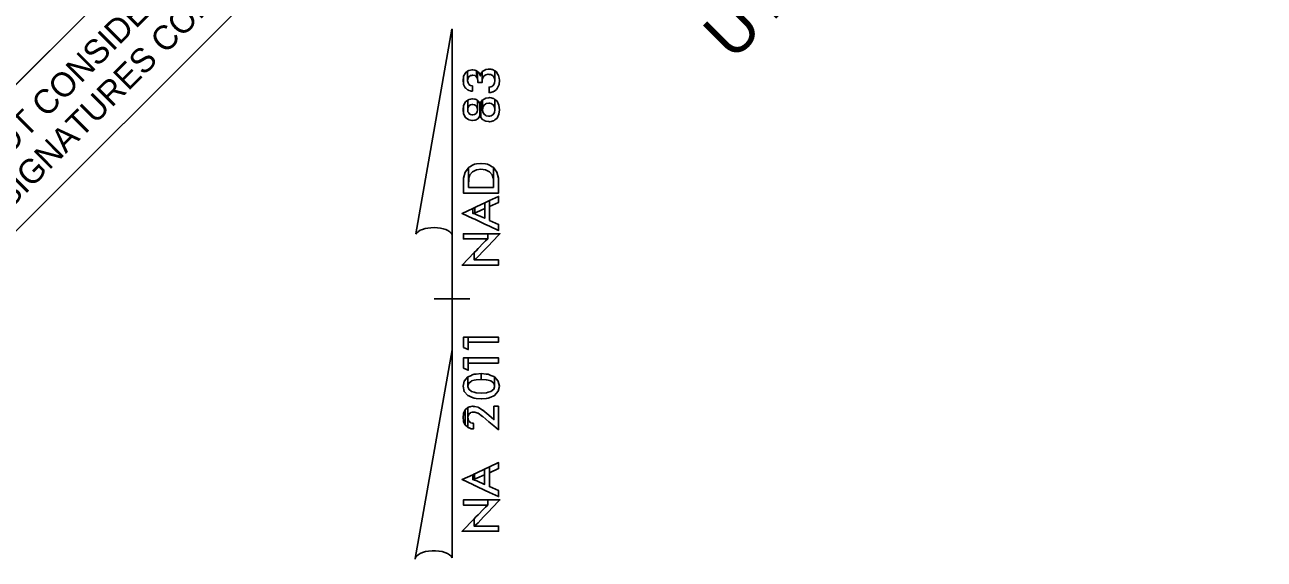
# Model space of a CAD drawing. Extents: x 1439200 to 1641361, y 392889 to 606444.
# Drawn here: x 1640975.9 to 1641088.2, y 393519.9 to 393568.3 of the extents above; entities that cross this region are included whole.
import ezdxf

# ---------------------------------------------------------------- set-up
doc = ezdxf.new("R2010")
doc.units = 0
for name, color, linetype in [('North Arrow NAD83 CELL', 7, 'Continuous'), ('Old_Level_60', 7, 'Continuous'), ('Sheet Sticker Exception Certification CELL', 7, 'Continuous'), ('UC Plan Sheet 34 CELL', 7, 'Continuous')]:
    doc.layers.add(name, color=color, linetype=linetype)

msp = doc.modelspace()

# ---------------------------------------------------------------- linework, layer by layer
at = {"layer": 'North Arrow NAD83 CELL'}
for p, q in [((1641011.28, 393549.32), (1641014.57, 393567.86)), ((1641014.59, 393567.86), (1641014.57, 393567.86)), ((1641014.59, 393567.86), (1641014.57, 393567.86)), ((1641014.59, 393567.86), (1641014.58, 393548.74)), ((1641014.58, 393538.82), (1641014.58, 393549.3)), ((1641014.58, 393548.74), (1641014.58, 393549.28)), ((1641012.98, 393543.46), (1641012.96, 393543.46)), ((1641014.4, 393543.46), (1641012.98, 393543.46)), ((1641013, 393543.46), (1641016.2, 393543.46)), ((1641014.58, 393538.82), (1641011.23, 393519.92)), ((1641014.59, 393520), (1641014.58, 393538.82))]:
    msp.add_line(p, q, dxfattribs=at)
for points in [[(1641016.38, 393562.26), (1641016.42, 393562.26), (1641016.42, 393562.73), (1641016.38, 393562.73), (1641016.26, 393562.76), (1641016.25, 393562.76), (1641016.25, 393562.76), (1641016.11, 393562.86), (1641016.1, 393562.87), (1641016.09, 393562.89), (1641016.03, 393563.01), (1641016.01, 393563.09), (1641016.01, 393563.11), (1641015.99, 393563.2), (1641015.99, 393564.07), (1641015.82, 393563.95), (1641015.77, 393563.87), (1641015.77, 393563.87), (1641015.63, 393563.63), (1641015.62, 393563.54), (1641015.62, 393562.88), (1641015.63, 393562.85), (1641015.77, 393562.57), (1641015.82, 393562.53), (1641015.99, 393562.38), (1641016.01, 393562.37), (1641016.01, 393562.37), (1641016.03, 393562.36), (1641016.09, 393562.34), (1641016.1, 393562.33), (1641016.11, 393562.33), (1641016.25, 393562.28), (1641016.25, 393562.28), (1641016.26, 393562.27)], [(1641016.74, 393563.59), (1641016.79, 393563.55), (1641016.79, 393564.1), (1641016.74, 393564.14), (1641016.63, 393564.15), (1641016.44, 393564.19), (1641016.42, 393564.19), (1641016.42, 393564.19), (1641016.38, 393564.19), (1641016.26, 393564.17), (1641016.25, 393564.16), (1641016.25, 393564.16), (1641016.25, 393564.16), (1641016.11, 393564.14), (1641016.1, 393564.14), (1641016.09, 393564.14), (1641016.03, 393564.09), (1641016.01, 393564.08), (1641016.01, 393564.08), (1641015.99, 393564.07), (1641015.99, 393563.2), (1641016.01, 393563.35), (1641016.01, 393563.4), (1641016.03, 393563.42), (1641016.09, 393563.55), (1641016.1, 393563.57), (1641016.11, 393563.57), (1641016.25, 393563.67), (1641016.25, 393563.67), (1641016.26, 393563.67), (1641016.38, 393563.69), (1641016.42, 393563.7), (1641016.42, 393563.7), (1641016.44, 393563.71), (1641016.63, 393563.67)], [(1641016.79, 393563.55), (1641016.88, 393563.39), (1641016.88, 393564.05), (1641016.79, 393564.1)], [(1641017.19, 393563.05), (1641017.32, 393563.05), (1641017.32, 393564.02), (1641017.19, 393563.85), (1641017.13, 393563.64), (1641017.09, 393563.79), (1641016.97, 393563.99), (1641016.9, 393564.03), (1641016.9, 393564.03), (1641016.88, 393564.05), (1641016.88, 393563.39), (1641016.9, 393563.19), (1641016.9, 393563.05), (1641016.97, 393563.05), (1641017.09, 393563.05), (1641017.13, 393563.05)], [(1641018.41, 393563.41), (1641018.45, 393563.24), (1641018.45, 393564.1), (1641018.41, 393564.12), (1641018.4, 393564.13), (1641018.4, 393564.13), (1641018.29, 393564.2), (1641018.27, 393564.21), (1641018.27, 393564.21), (1641018.19, 393564.22), (1641018.08, 393564.24), (1641018.07, 393564.24), (1641017.95, 393564.26), (1641017.86, 393564.25), (1641017.65, 393564.22), (1641017.63, 393564.22), (1641017.49, 393564.14), (1641017.37, 393564.08), (1641017.36, 393564.08), (1641017.32, 393564.03), (1641017.32, 393564.02), (1641017.32, 393563.15), (1641017.32, 393563.3), (1641017.36, 393563.47), (1641017.37, 393563.49), (1641017.49, 393563.65), (1641017.63, 393563.74), (1641017.65, 393563.75), (1641017.86, 393563.79), (1641017.95, 393563.78), (1641018.07, 393563.77), (1641018.08, 393563.76), (1641018.19, 393563.71), (1641018.27, 393563.67), (1641018.27, 393563.66), (1641018.29, 393563.63), (1641018.4, 393563.48)], [(1641018.84, 393562.85), (1641018.87, 393563.25), (1641018.84, 393563.43), (1641018.8, 393563.67), (1641018.68, 393563.86), (1641018.6, 393564), (1641018.45, 393564.09), (1641018.45, 393564.1), (1641018.45, 393563.24), (1641018.41, 393562.94), (1641018.4, 393562.92), (1641018.29, 393562.76), (1641018.27, 393562.74), (1641018.27, 393562.73), (1641018.19, 393562.69), (1641018.08, 393562.64), (1641018.07, 393562.64), (1641017.95, 393562.63), (1641017.94, 393562.63), (1641017.94, 393562.13), (1641017.95, 393562.13), (1641018.07, 393562.15), (1641018.09, 393562.15), (1641018.19, 393562.17), (1641018.27, 393562.2), (1641018.27, 393562.2), (1641018.29, 393562.21), (1641018.4, 393562.25), (1641018.41, 393562.26), (1641018.45, 393562.27), (1641018.45, 393562.28), (1641018.6, 393562.42), (1641018.68, 393562.51), (1641018.8, 393562.75)], [(1641015.58, 393563.25), (1641015.62, 393562.88), (1641015.62, 393563.54)], [(1641016.84, 393560.78), (1641016.87, 393560.58), (1641016.87, 393561.43), (1641016.84, 393561.45), (1641016.75, 393561.5), (1641016.68, 393561.53), (1641016.68, 393561.53), (1641016.61, 393561.54), (1641016.44, 393561.56), (1641016.44, 393561.56), (1641016.37, 393561.56), (1641016.26, 393561.53), (1641016.11, 393561.49), (1641016.11, 393561.49), (1641016.06, 393561.48), (1641016.02, 393561.45), (1641016, 393561.43), (1641016, 393560.58), (1641016.02, 393560.76), (1641016.06, 393560.83), (1641016.11, 393560.92), (1641016.11, 393560.92), (1641016.26, 393561.03), (1641016.38, 393561.05), (1641016.44, 393561.06), (1641016.61, 393561.03), (1641016.68, 393560.98), (1641016.68, 393560.98), (1641016.75, 393560.94)], [(1641018.83, 393560.18), (1641018.87, 393560.58), (1641018.83, 393560.98), (1641018.83, 393560.99), (1641018.66, 393561.34), (1641018.66, 393561.34), (1641018.45, 393561.51), (1641018.45, 393560.58), (1641018.42, 393560.33), (1641018.37, 393560.24), (1641018.37, 393560.24), (1641018.31, 393560.14), (1641018.13, 393560.03), (1641018.01, 393560), (1641018.01, 393560), (1641017.9, 393559.98), (1641017.67, 393560.03), (1641017.65, 393560.04), (1641017.48, 393560.16), (1641017.48, 393560.16), (1641017.37, 393560.36), (1641017.36, 393560.46), (1641017.35, 393560.51), (1641017.34, 393560.58), (1641017.34, 393561.46), (1641017.18, 393561.27), (1641017.19, 393559.88), (1641017.35, 393559.69), (1641017.35, 393559.68), (1641017.36, 393559.68), (1641017.37, 393559.67), (1641017.48, 393559.62), (1641017.48, 393559.61), (1641017.65, 393559.53), (1641017.67, 393559.53), (1641017.9, 393559.5), (1641018.01, 393559.49), (1641018.01, 393559.49), (1641018.13, 393559.52), (1641018.31, 393559.57), (1641018.37, 393559.58), (1641018.42, 393559.63), (1641018.45, 393559.65), (1641018.66, 393559.82), (1641018.66, 393559.82), (1641018.83, 393560.17)], [(1641018.42, 393560.83), (1641018.45, 393560.58), (1641018.45, 393561.51), (1641018.42, 393561.53), (1641018.37, 393561.58), (1641018.31, 393561.59), (1641018.12, 393561.64), (1641018.01, 393561.67), (1641018.01, 393561.67), (1641017.9, 393561.66), (1641017.9, 393561.66), (1641017.67, 393561.63), (1641017.65, 393561.63), (1641017.48, 393561.54), (1641017.48, 393561.54), (1641017.37, 393561.48), (1641017.36, 393561.48), (1641017.35, 393561.47), (1641017.34, 393561.46), (1641017.34, 393560.58), (1641017.35, 393560.64), (1641017.36, 393560.7), (1641017.37, 393560.8), (1641017.48, 393561), (1641017.48, 393561), (1641017.65, 393561.12), (1641017.67, 393561.14), (1641017.9, 393561.17), (1641018.01, 393561.16), (1641018.01, 393561.16), (1641018.12, 393561.14), (1641018.31, 393561.02), (1641018.37, 393560.92)], [(1641015.63, 393560.23), (1641015.63, 393560.19), (1641015.63, 393560.97), (1641015.63, 393560.96), (1641015.58, 393560.58), (1641015.58, 393560.58)], [(1641017.03, 393559.9), (1641017.11, 393560.05), (1641017.11, 393561.11), (1641017.03, 393561.27), (1641017.02, 393561.28), (1641016.9, 393561.41), (1641016.9, 393561.42), (1641016.87, 393561.43), (1641016.87, 393560.58), (1641016.84, 393560.38), (1641016.75, 393560.23), (1641016.68, 393560.18), (1641016.68, 393560.18), (1641016.68, 393560.18), (1641016.61, 393560.13), (1641016.44, 393560.1), (1641016.38, 393560.11), (1641016.26, 393560.13), (1641016.11, 393560.24), (1641016.11, 393560.25), (1641016.06, 393560.33), (1641016.02, 393560.4), (1641016, 393560.58), (1641016, 393561.43), (1641015.8, 393561.29), (1641015.63, 393560.97), (1641015.63, 393560.19), (1641015.8, 393559.87), (1641016, 393559.73), (1641016.02, 393559.71), (1641016.06, 393559.68), (1641016.11, 393559.67), (1641016.11, 393559.67), (1641016.26, 393559.63), (1641016.38, 393559.6), (1641016.44, 393559.6), (1641016.61, 393559.62), (1641016.68, 393559.63), (1641016.68, 393559.63), (1641016.75, 393559.67), (1641016.84, 393559.71), (1641016.87, 393559.73), (1641016.9, 393559.74), (1641016.9, 393559.74), (1641017.02, 393559.89)], [(1641017.18, 393559.9), (1641017.19, 393559.88), (1641017.18, 393561.27), (1641017.18, 393561.27), (1641017.11, 393561.11), (1641017.11, 393560.05)], [(1641018.78, 393553.02), (1641018.8, 393553.02), (1641018.8, 393553.72), (1641018.78, 393554.38), (1641018.64, 393554.92), (1641018.33, 393555.33), (1641018.33, 393553.54), (1641018.32, 393553.54), (1641018.3, 393553.54), (1641018.22, 393553.54), (1641017.98, 393553.54), (1641017.79, 393553.54), (1641017.62, 393553.54), (1641017.21, 393553.54), (1641017.2, 393553.54), (1641016.79, 393553.54), (1641016.62, 393553.54), (1641016.43, 393553.54), (1641016.19, 393553.54), (1641016.11, 393553.54), (1641016.09, 393553.54), (1641016.08, 393553.54), (1641016.07, 393555.32), (1641015.77, 393554.92), (1641015.63, 393554.38), (1641015.61, 393553.72), (1641015.61, 393553.02), (1641015.63, 393553.02), (1641015.77, 393553.02), (1641016.08, 393553.02), (1641016.09, 393553.02), (1641016.11, 393553.02), (1641016.19, 393553.02), (1641016.43, 393553.02), (1641016.62, 393553.02), (1641016.79, 393553.02), (1641017.2, 393553.02), (1641017.21, 393553.02), (1641017.62, 393553.02), (1641017.79, 393553.02), (1641017.98, 393553.02), (1641018.22, 393553.02), (1641018.3, 393553.02), (1641018.32, 393553.02), (1641018.33, 393553.02), (1641018.64, 393553.02)], [(1641018.3, 393554.39), (1641018.32, 393554.32), (1641018.32, 393555.34), (1641018.3, 393555.37), (1641018.22, 393555.41), (1641017.98, 393555.54), (1641017.79, 393555.64), (1641017.62, 393555.66), (1641017.62, 393555.66), (1641017.2, 393555.72), (1641017.2, 393555.72), (1641016.79, 393555.66), (1641016.62, 393555.64), (1641016.43, 393555.54), (1641016.18, 393555.41), (1641016.11, 393555.37), (1641016.09, 393555.34), (1641016.07, 393555.32), (1641016.08, 393553.72), (1641016.09, 393554.32), (1641016.11, 393554.4), (1641016.19, 393554.67), (1641016.43, 393554.96), (1641016.62, 393555.05), (1641016.79, 393555.13), (1641017.2, 393555.18), (1641017.2, 393555.18), (1641017.62, 393555.13), (1641017.79, 393555.05), (1641017.98, 393554.96), (1641018.22, 393554.67)], [(1641018.32, 393554.32), (1641018.33, 393553.72), (1641018.33, 393555.33), (1641018.32, 393555.34)], [(1641017.98, 393551.81), (1641018.8, 393552.18), (1641018.8, 393552.72), (1641017.98, 393552.34)], [(1641017.98, 393550.02), (1641018.8, 393549.64), (1641018.8, 393550.19), (1641017.98, 393550.55), (1641017.98, 393552.34), (1641017.54, 393552.14), (1641017.54, 393550.75), (1641016.82, 393551.07), (1641016.82, 393551.07), (1641016.64, 393551.14), (1641016.63, 393551.14), (1641016.46, 393551.19), (1641016.46, 393551.63), (1641015.49, 393551.18), (1641016.46, 393550.73), (1641016.63, 393550.65), (1641016.64, 393550.65), (1641016.82, 393550.56), (1641016.82, 393550.56), (1641017.54, 393550.22)], [(1641016.46, 393551.19), (1641016.63, 393551.24), (1641016.63, 393551.71), (1641016.46, 393551.63)], [(1641016.82, 393551.31), (1641017.54, 393551.63), (1641017.54, 393552.14), (1641016.82, 393551.8), (1641016.82, 393551.8), (1641016.64, 393551.72), (1641016.63, 393551.71), (1641016.63, 393551.24), (1641016.64, 393551.24), (1641016.82, 393551.31)], [(1641017.61, 393548.87), (1641017.82, 393548.87), (1641017.82, 393549.34), (1641017.61, 393549.34), (1641017.44, 393549.34), (1641016.94, 393549.34), (1641016.75, 393549.34), (1641015.61, 393549.34), (1641015.61, 393548.87), (1641016.75, 393548.87), (1641016.94, 393548.87), (1641017.44, 393548.87)], [(1641018.8, 393549.21), (1641018.92, 393549.34), (1641018.8, 393549.34), (1641017.82, 393549.34), (1641017.82, 393548.87), (1641017.61, 393548.69), (1641017.44, 393548.52), (1641016.94, 393548), (1641016.75, 393547.8), (1641016.59, 393547.64), (1641016.59, 393546.97), (1641016.75, 393547.1), (1641016.94, 393547.28), (1641017.44, 393547.8), (1641017.61, 393547.98), (1641017.82, 393548.2)], [(1641017.82, 393546.5), (1641018.8, 393546.5), (1641018.8, 393546.97), (1641017.82, 393546.97), (1641017.61, 393546.97), (1641017.44, 393546.97), (1641016.94, 393546.97), (1641016.75, 393546.97), (1641016.59, 393546.97), (1641016.59, 393547.64), (1641015.49, 393546.5), (1641016.59, 393546.5), (1641016.75, 393546.5), (1641016.94, 393546.5), (1641017.44, 393546.5), (1641017.61, 393546.5)], [(1641015.63, 393539.05), (1641016.04, 393538.85), (1641016.04, 393539.98), (1641015.63, 393539.98)], [(1641016.04, 393539.51), (1641018.78, 393539.51), (1641018.78, 393539.98), (1641016.04, 393539.98)], [(1641015.63, 393537.18), (1641016.04, 393536.98), (1641016.04, 393538.11), (1641015.63, 393538.11)], [(1641016.04, 393537.63), (1641018.78, 393537.63), (1641018.78, 393538.11), (1641016.04, 393538.11)], [(1641018.77, 393535.07), (1641018.87, 393535.53), (1641018.77, 393535.97), (1641018.77, 393535.99), (1641018.42, 393536.37), (1641018.42, 393535.52), (1641018.42, 393535.5), (1641018.41, 393535.49), (1641018.35, 393535.25), (1641018.09, 393535.05), (1641018.09, 393535.05), (1641018.09, 393535.05), (1641017.86, 393534.99), (1641017.86, 393534.99), (1641017.69, 393534.94), (1641017.68, 393534.94), (1641017.22, 393534.9), (1641017.22, 393534.9), (1641017.21, 393534.9), (1641016.75, 393534.94), (1641016.58, 393534.98), (1641016.58, 393534.99), (1641016.35, 393535.05), (1641016.35, 393535.05), (1641016.09, 393535.25), (1641016.02, 393535.5), (1641016.02, 393535.51), (1641016.01, 393535.54), (1641016.01, 393536.37), (1641015.67, 393536), (1641015.67, 393535.98), (1641015.57, 393535.53), (1641015.57, 393535.53), (1641015.67, 393535.06), (1641015.67, 393535.05), (1641016.01, 393534.69), (1641016.02, 393534.68), (1641016.02, 393534.68), (1641016.09, 393534.65), (1641016.35, 393534.54), (1641016.35, 393534.54), (1641016.58, 393534.45), (1641016.58, 393534.45), (1641016.75, 393534.43), (1641017.21, 393534.38), (1641017.22, 393534.38), (1641017.22, 393534.38), (1641017.68, 393534.43), (1641017.69, 393534.43), (1641017.86, 393534.45), (1641017.86, 393534.45), (1641018.09, 393534.54), (1641018.09, 393534.54), (1641018.35, 393534.65), (1641018.41, 393534.67), (1641018.42, 393534.68), (1641018.42, 393534.68), (1641018.77, 393535.07)], [(1641016.75, 393536.12), (1641017.21, 393536.15), (1641017.21, 393536.67), (1641016.75, 393536.62), (1641016.58, 393536.61), (1641016.57, 393536.61), (1641016.57, 393536.61), (1641016.35, 393536.52), (1641016.35, 393536.52), (1641016.34, 393536.51), (1641016.09, 393536.41), (1641016.09, 393536.41), (1641016.02, 393536.38), (1641016.02, 393536.38), (1641016.01, 393536.37), (1641016.01, 393535.54), (1641016.02, 393535.56), (1641016.02, 393535.56), (1641016.09, 393535.81), (1641016.34, 393536), (1641016.35, 393536.01), (1641016.57, 393536.07), (1641016.58, 393536.07)], [(1641018.42, 393535.54), (1641018.42, 393535.52), (1641018.42, 393536.37), (1641018.42, 393536.37), (1641018.41, 393536.38), (1641018.35, 393536.4), (1641018.09, 393536.51), (1641018.09, 393536.51), (1641017.86, 393536.61), (1641017.86, 393536.61), (1641017.69, 393536.62), (1641017.68, 393536.62), (1641017.22, 393536.67), (1641017.22, 393536.67), (1641017.21, 393536.67), (1641017.21, 393536.15), (1641017.22, 393536.15), (1641017.22, 393536.15), (1641017.68, 393536.12), (1641017.69, 393536.12), (1641017.86, 393536.07), (1641017.86, 393536.07), (1641018.09, 393536.01), (1641018.09, 393536.01), (1641018.35, 393535.81), (1641018.41, 393535.55)], [(1641015.76, 393532.03), (1641016, 393531.81), (1641016, 393533.59), (1641015.76, 393533.39)], [(1641016.45, 393531.67), (1641016.51, 393531.66), (1641016.51, 393532.16), (1641016.45, 393532.17), (1641016.43, 393532.17), (1641016.42, 393532.17), (1641016.28, 393532.22), (1641016.27, 393532.23), (1641016.24, 393532.25), (1641016.13, 393532.34), (1641016.1, 393532.4), (1641016.04, 393532.52), (1641016.03, 393532.53), (1641016.02, 393532.78), (1641016.02, 393533.61), (1641016, 393533.59), (1641016, 393531.8), (1641016.02, 393531.79), (1641016.03, 393531.79), (1641016.04, 393531.79), (1641016.1, 393531.76), (1641016.13, 393531.75), (1641016.24, 393531.7), (1641016.27, 393531.68), (1641016.28, 393531.68), (1641016.42, 393531.67), (1641016.43, 393531.67)], [(1641018.37, 393531.93), (1641018.78, 393531.59), (1641018.78, 393533.72), (1641018.37, 393533.72), (1641018.37, 393532.51), (1641017.9, 393532.91), (1641017.36, 393533.36), (1641017.35, 393533.36), (1641016.93, 393533.62), (1641016.93, 393533.61), (1641016.92, 393533.62), (1641016.65, 393533.68), (1641016.51, 393533.7), (1641016.45, 393533.71), (1641016.43, 393533.71), (1641016.42, 393533.71), (1641016.28, 393533.68), (1641016.27, 393533.68), (1641016.24, 393533.67), (1641016.13, 393533.65), (1641016.13, 393533.65), (1641016.1, 393533.64), (1641016.04, 393533.63), (1641016.03, 393533.62), (1641016.02, 393533.61), (1641016.02, 393532.78), (1641016.03, 393532.8), (1641016.04, 393532.82), (1641016.1, 393532.99), (1641016.13, 393533.02), (1641016.24, 393533.13), (1641016.27, 393533.14), (1641016.28, 393533.15), (1641016.42, 393533.19), (1641016.43, 393533.19), (1641016.45, 393533.19), (1641016.51, 393533.19), (1641016.65, 393533.19), (1641016.92, 393533.08), (1641016.93, 393533.08), (1641017.35, 393532.78), (1641017.36, 393532.78), (1641017.9, 393532.32)], [(1641015.76, 393532.04), (1641015.76, 393532.03), (1641015.76, 393533.39), (1641015.76, 393533.38), (1641015.62, 393533.08), (1641015.61, 393533.05), (1641015.57, 393532.68), (1641015.57, 393532.68), (1641015.61, 393532.43), (1641015.62, 393532.32)], [(1641017.97, 393525.91), (1641018.79, 393525.53), (1641018.79, 393526.08), (1641017.97, 393526.44), (1641017.97, 393528.23), (1641017.53, 393528.03), (1641017.53, 393526.64), (1641016.81, 393526.96), (1641016.81, 393526.96), (1641016.63, 393527.03), (1641016.62, 393527.03), (1641016.45, 393527.08), (1641016.45, 393527.52), (1641015.48, 393527.07), (1641016.45, 393526.62), (1641016.62, 393526.54), (1641016.63, 393526.54), (1641016.81, 393526.45), (1641016.81, 393526.45), (1641017.53, 393526.12)], [(1641016.81, 393527.2), (1641017.53, 393527.52), (1641017.53, 393528.03), (1641016.81, 393527.69), (1641016.81, 393527.69), (1641016.63, 393527.61), (1641016.62, 393527.6), (1641016.62, 393527.13), (1641016.63, 393527.13), (1641016.81, 393527.2)], [(1641017.97, 393527.7), (1641018.79, 393528.07), (1641018.79, 393528.61), (1641017.97, 393528.23)], [(1641016.45, 393527.08), (1641016.62, 393527.13), (1641016.62, 393527.6), (1641016.45, 393527.52)], [(1641017.6, 393524.76), (1641017.81, 393524.76), (1641017.81, 393525.23), (1641017.6, 393525.23), (1641017.43, 393525.23), (1641016.93, 393525.23), (1641016.74, 393525.23), (1641015.6, 393525.23), (1641015.6, 393524.76), (1641016.74, 393524.76), (1641016.93, 393524.76), (1641017.43, 393524.76)], [(1641018.79, 393525.11), (1641018.91, 393525.23), (1641018.79, 393525.23), (1641017.81, 393525.23), (1641017.81, 393524.76), (1641017.6, 393524.58), (1641017.43, 393524.41), (1641016.93, 393523.89), (1641016.74, 393523.7), (1641016.58, 393523.53), (1641016.58, 393522.86), (1641016.74, 393522.99), (1641016.93, 393523.17), (1641017.43, 393523.69), (1641017.6, 393523.87), (1641017.81, 393524.09)], [(1641017.81, 393522.39), (1641018.79, 393522.39), (1641018.79, 393522.86), (1641017.81, 393522.86), (1641017.6, 393522.86), (1641017.43, 393522.86), (1641016.93, 393522.86), (1641016.74, 393522.86), (1641016.58, 393522.86), (1641016.58, 393523.53), (1641015.48, 393522.39), (1641016.58, 393522.39), (1641016.74, 393522.39), (1641016.93, 393522.39), (1641017.43, 393522.39), (1641017.6, 393522.39)]]:
    msp.add_lwpolyline(points, close=True, dxfattribs=at)
for centre, start_param, end_param in [((1641012.94, 393549.12), 0.216388, 2.908219), ((1641012.93, 393519.85), 0.201328, 3.141593)]:
    msp.add_ellipse(centre, major_axis=(1.69, -0.01), ratio=0.461098, start_param=start_param, end_param=end_param, dxfattribs=at)
at = {"layer": 'Old_Level_60'}
msp.add_lwpolyline([(1640939.64, 393550.94), (1640996.29, 393607.45), (1641007.98, 393595.72), (1640951.33, 393539.22)], close=True, dxfattribs=at)
at = {"layer": 'Sheet Sticker Exception Certification CELL'}
for p, q in [((1640951.33, 393539.22), (1641007.98, 393595.72)), ((1641014.62, 393589.07), (1640957.97, 393532.56))]:
    msp.add_line(p, q, dxfattribs=at)

# ---------------------------------------------------------------- texts
for s, p in [('DOCUMENT NOT CONSIDERED FINAL', (1640960.22, 393542.24)), ('UNLESS ALL SIGNATURES COMPLETED', (1640961.27, 393538.31))]:
    msp.add_text(s, height=2.2, rotation=44.9279, dxfattribs=at).set_placement(p)
at = {"layer": 'UC Plan Sheet 34 CELL'}
msp.add_text('UTILITY CONSTRUCTION', height=4.25, rotation=44.9279, dxfattribs=at).set_placement((1641040.01, 393564.89))

doc.saveas('drawing.dxf')
